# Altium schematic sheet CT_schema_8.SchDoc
size 277 x 170 mm
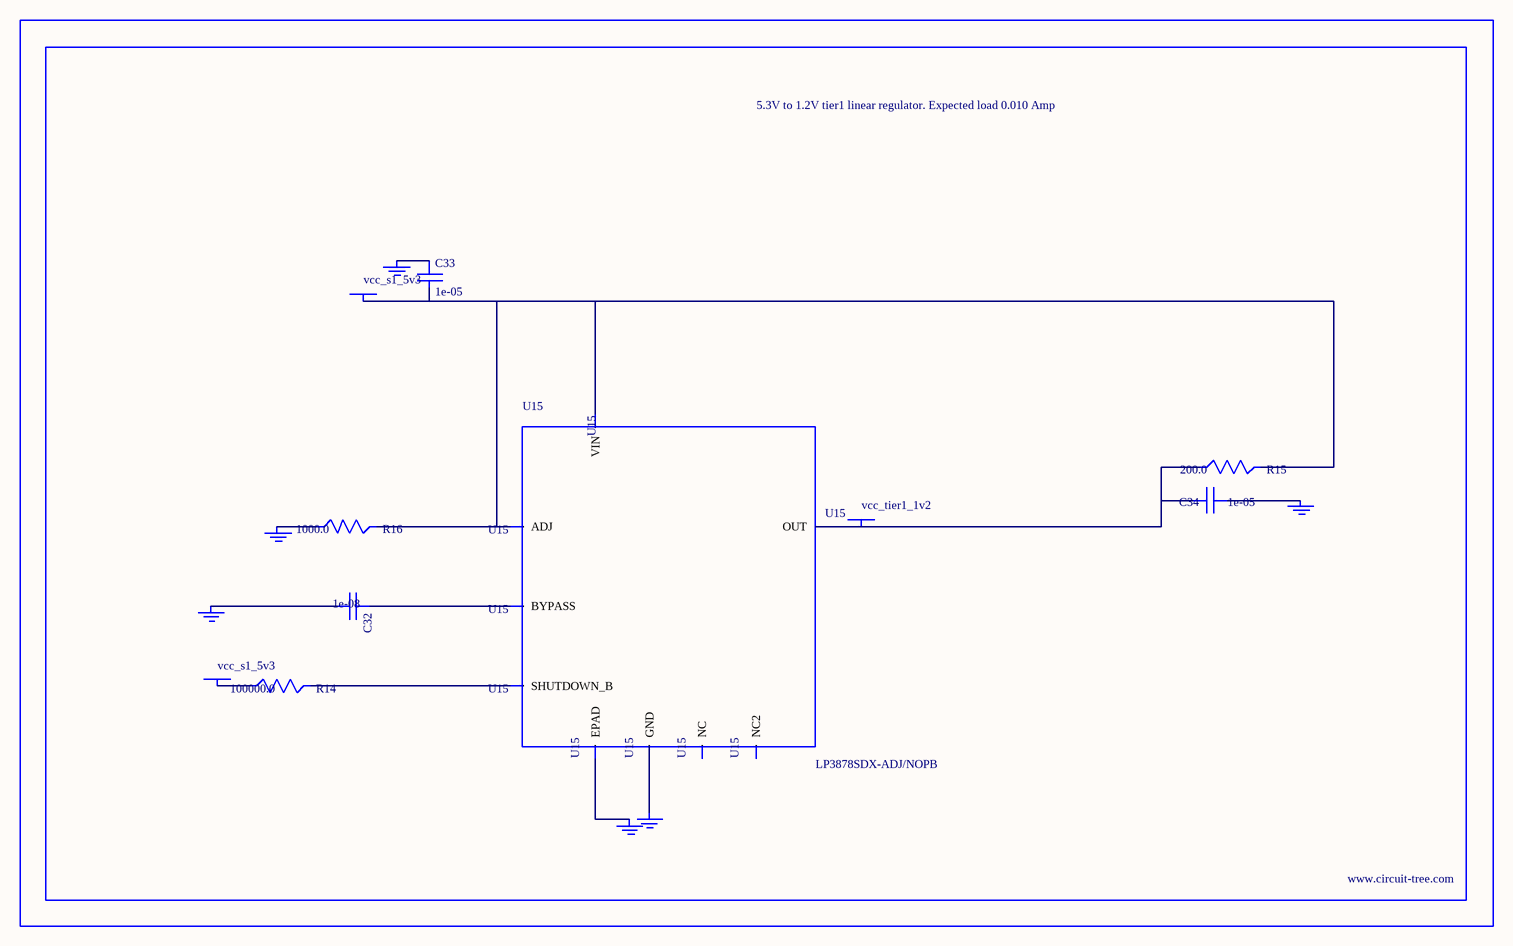
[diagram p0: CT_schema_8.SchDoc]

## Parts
BORDER7  (no value)
C32  1e-08  [C0402]
C33  1e-05  [C1206]
C34  1e-05  [C0805]
GND_INSTANCE_7_0  (no value)
GND_INSTANCE_7_1  (no value)
GND_INSTANCE_7_2  (no value)
GND_INSTANCE_7_3  (no value)
GND_INSTANCE_7_4  (no value)
GND_INSTANCE_7_5  (no value)
POWER_INSTANCE_7_0  vcc_s1_5v3
POWER_INSTANCE_7_1  vcc_s1_5v3
POWER_INSTANCE_7_2  vcc_tier1_1v2
R14  100000.0  [R0603]
R15  200.0  [R0603]
R16  1000.0  [R0603]
U15  LP3878SDX-ADJ/NOPB  [WSON-8]

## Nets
NetC32_1: C32.1 U15.1(BYPASS)
NetC32_2: C32.2 GND_INSTANCE_7_0.0(GND)
NetC33_1: C33.1 GND_INSTANCE_7_1.0(GND)
NetC33_2: C33.2 POWER_INSTANCE_7_0.0(PWR) R15.2 R16.2 U15.4(VIN) U15.6(ADJ)
NetC34_1: C34.1 GND_INSTANCE_7_2.0(GND)
NetC34_2: C34.2 POWER_INSTANCE_7_2.0(PWR) R15.1 U15.5(OUT)
NetGND_INSTANCE_7_3_0: GND_INSTANCE_7_3.0(GND) R16.1
NetGND_INSTANCE_7_4_0: GND_INSTANCE_7_4.0(GND) U15.PAD(EPAD)
NetGND_INSTANCE_7_5_0: GND_INSTANCE_7_5.0(GND) U15.3(GND)
NetPOWER_INSTANCE_7_1_0: POWER_INSTANCE_7_1.0(PWR) R14.1
NetR14_2: R14.2 U15.8(SHUTDOWN_B)

Not connected (* = marked no-connect by the designer): U15 2(NC) 7(NC2)

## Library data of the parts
BORDER7 = BORDER_PAGE7
C32 = C0402C103K3RAC
C33 = C1206C106K3RACTU
C34 = GRM219R60J106ME19D
GND_INSTANCE_7_0-GND_INSTANCE_7_5 = GND
POWER_INSTANCE_7_0-POWER_INSTANCE_7_2 = PWR
R14 = RC0603JR-07100KL
R15 = RC0603JR-07200RL
R16 = RC0603JR-071KL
